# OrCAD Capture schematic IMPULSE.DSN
size A
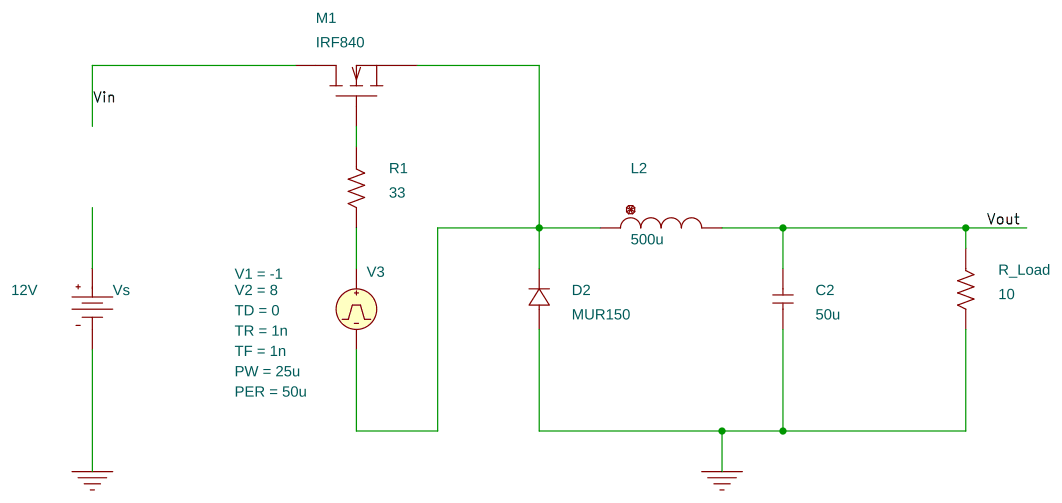
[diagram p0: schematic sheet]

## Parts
C2  50u  [RAD/CK05]
D2  MUR150  [DO-41]
L2  500u  [DISC/.350x.175/LS.200x.100/.034]
M1  IRF840  [TO220AB]
R1  33  [AX/RC05]
R_Load  10  [AX/RC05]
V3  VPULSE
Vs  VDC

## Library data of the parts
C2 = C: IC: 1m
D2 = MUR150
L2 = L
M1 = IRFZ34
R1 R_Load = R
V3 = VPULSE: PER: 50u; PW: 25u; TD: 0; TF: 1n; TR: 1n; V1: -1; V2: 8
Vs = VDC: DC: 12V

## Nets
Vin: M1.2(d)
0: C2.2 D2.1 R_Load.2 Vs.1(-)
Vout: C2.1 L2.2 R_Load.1
N9001238: D2.2 L2.1 M1.3(s) V3.2(-)
N9001912: R1.2 V3.1(+)
N9003868: M1.1(g) R1.1

Not connected (* = marked no-connect by the designer): Vs 0(+)
